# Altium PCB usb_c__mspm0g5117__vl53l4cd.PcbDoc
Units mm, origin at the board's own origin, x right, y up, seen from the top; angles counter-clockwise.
Board outline 68 x 40 mm, 2 copper layers (Top, Bottom), stack 0 mm thick; 34 components, 27 nets, 182 pads, 68 vias.
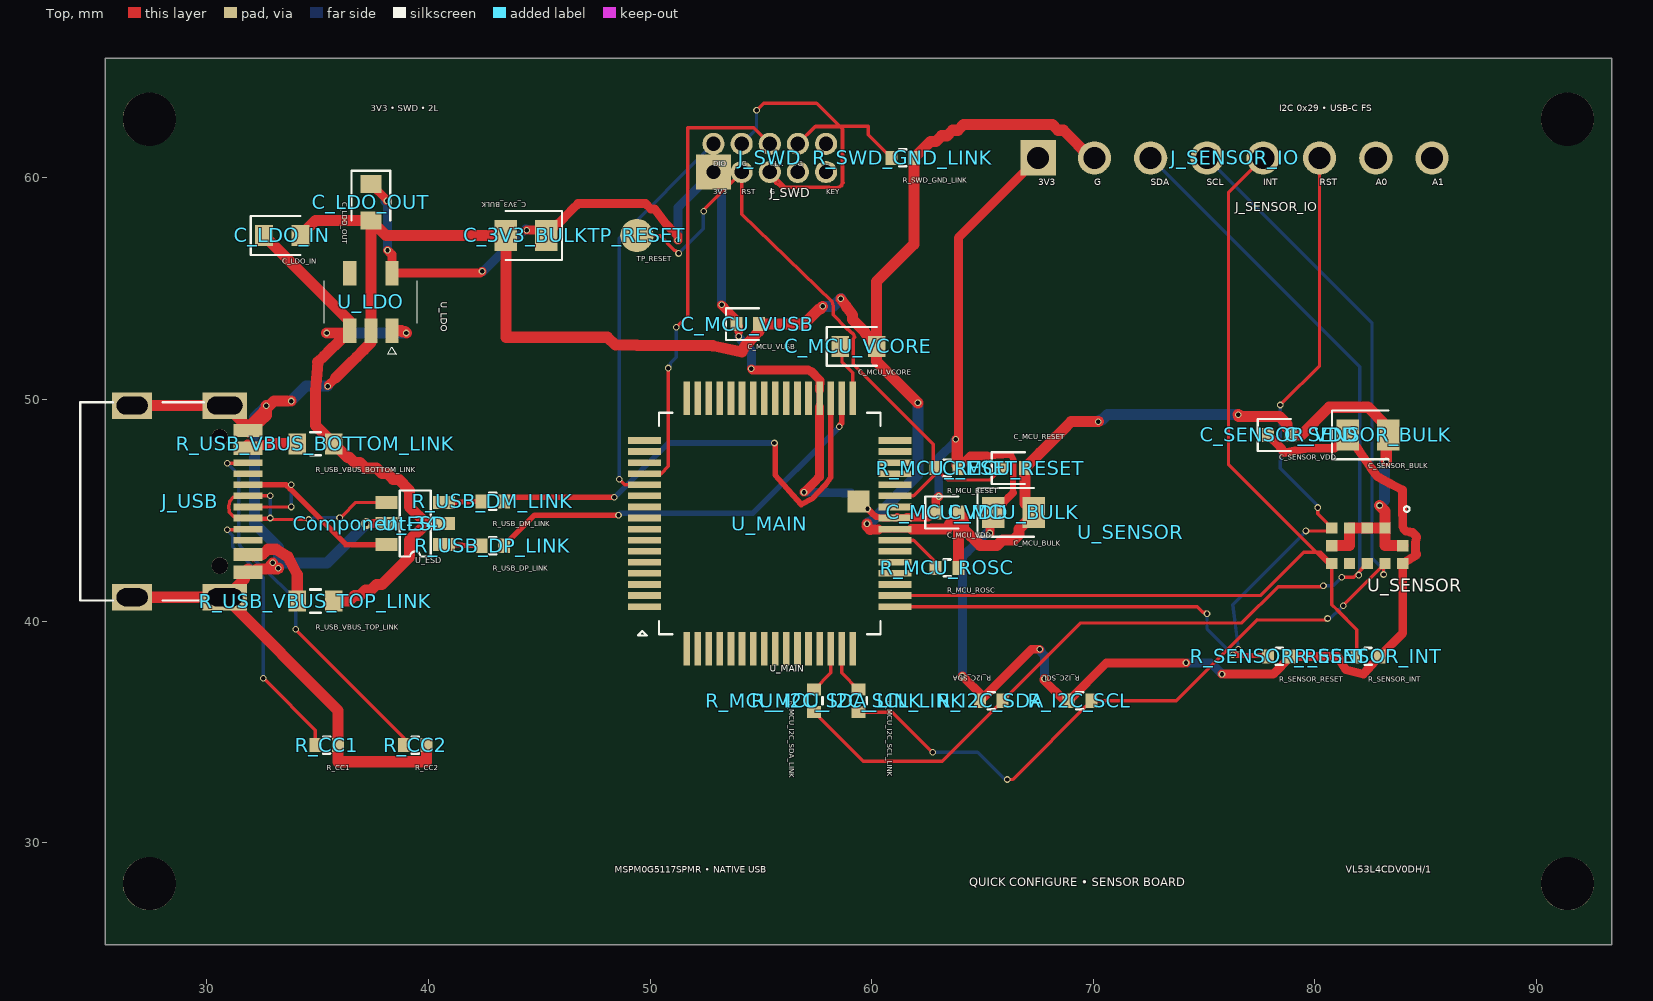
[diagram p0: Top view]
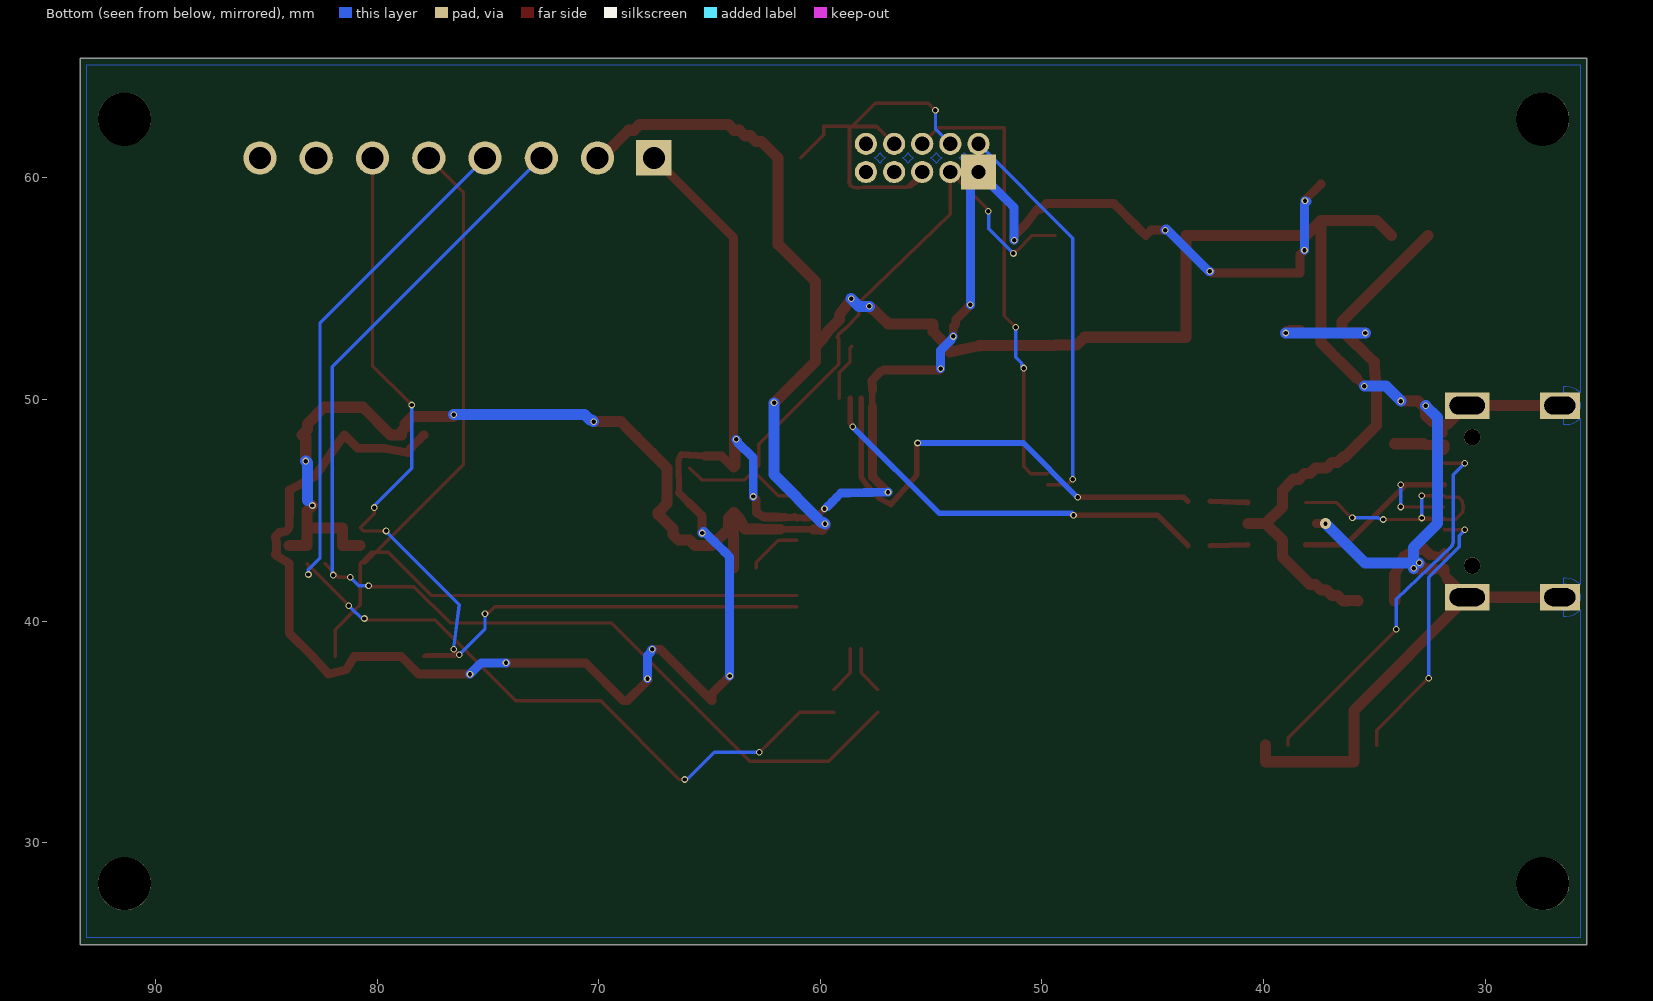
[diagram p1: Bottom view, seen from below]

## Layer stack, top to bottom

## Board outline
25.4,65.4 93.4,65.4 93.4,25.4 25.4,25.4

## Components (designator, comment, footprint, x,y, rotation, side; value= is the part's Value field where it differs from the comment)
C_3V3_BULK "" TSCIRCUIT-2.8500x1.4000mm 44.4,57.4 r180 top
C_LDO_IN "" TSCIRCUIT-2.4500x0.9500mm 33.4,57.4 r0 top
C_LDO_OUT "" TSCIRCUIT-0.9500x2.4500mm 37.4,58.9 r270 top
C_MCU_BULK "" TSCIRCUIT-2.8500x1.4000mm 66.4,44.9 r0 top
C_MCU_RESET "" TSCIRCUIT-1.5600x0.6400mm 66.4,46.9 r0 top
C_MCU_VCORE "" TSCIRCUIT-2.4500x0.9500mm 59.4,52.4 r0 top
C_MCU_VDD "" TSCIRCUIT-1.5600x0.6400mm 63.4,44.9 r0 top
C_MCU_VUSB "" TSCIRCUIT-1.5600x0.6400mm 54.4,53.4 r0 top
C_SENSOR_BULK "" TSCIRCUIT-2.8500x1.4000mm 82.4,48.4 r0 top
C_SENSOR_VDD "" TSCIRCUIT-1.5600x0.6400mm 78.4,48.4 r0 top
Component-34 "" TSCIRCUIT-0.5000x0.5000mm 37.2,44.4 r0 top
J_SENSOR_IO "" TSCIRCUIT-19.2800x1.5000mm 76.4,60.9 r0 top
J_SWD "" TSCIRCUIT-6.0800x2.2700mm 55.4,60.9 r0 top
J_USB "" TSCIRCUIT-6.7732x9.8502mm 29.112,45.4 r90 top
R_CC1 "" TSCIRCUIT-1.5600x0.6400mm 35.4,34.4 r0 top
R_CC2 "" TSCIRCUIT-1.5600x0.6400mm 39.4,34.4 r0 top
R_I2C_SCL "" TSCIRCUIT-1.5600x0.6400mm 69.4,36.4 r180 top
R_I2C_SDA "" TSCIRCUIT-1.5600x0.6400mm 65.4,36.4 r180 top
R_MCU_I2C_SCL_LINK "" TSCIRCUIT-0.6400x1.5600mm 59.4,36.4 r270 top
R_MCU_I2C_SDA_LINK "" TSCIRCUIT-0.6400x1.5600mm 57.4,36.4 r270 top
R_MCU_RESET "" TSCIRCUIT-1.5600x0.6400mm 63.4,46.9 r0 top
R_MCU_ROSC "" TSCIRCUIT-1.5600x0.6400mm 63.4,42.4 r0 top
R_SENSOR_INT "" TSCIRCUIT-1.5600x0.6400mm 82.4,38.4 r0 top
R_SENSOR_RESET "" TSCIRCUIT-1.5600x0.6400mm 78.4,38.4 r0 top
R_SWD_GND_LINK "" TSCIRCUIT-1.5600x0.6400mm 61.4,60.9 r0 top
R_USB_DM_LINK "" TSCIRCUIT-1.5600x0.6400mm 42.9,45.4 r0 top
R_USB_DP_LINK "" TSCIRCUIT-1.5600x0.6400mm 42.9,43.4 r0 top
R_USB_VBUS_BOTTOM_LINK "" TSCIRCUIT-2.4500x0.9500mm 34.9,48 r0 top
R_USB_VBUS_TOP_LINK "" TSCIRCUIT-2.4500x0.9500mm 34.9,40.9 r0 top
TP_RESET "" TSCIRCUIT-1.5000x1.5000mm 49.4,57.4 r0 top
U_ESD "" TSCIRCUIT-3.6000x2.5000mm 39.4,44.4 r0 top
U_LDO "" TSCIRCUIT-2.5000x3.7000mm 37.4,54.4 r270 top
U_MAIN "" TSCIRCUIT-12.8000x12.8000mm 55.4,44.4 r0 top
U_SENSOR "" TSCIRCUIT-3.7081x2.1079mm 82.368,43.4 r0 top

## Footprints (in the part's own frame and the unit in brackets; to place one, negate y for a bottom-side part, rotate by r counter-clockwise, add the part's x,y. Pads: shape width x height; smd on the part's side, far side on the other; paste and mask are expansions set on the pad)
TSCIRCUIT-0.5000x0.5000mm [mm]
TSCIRCUIT-0.6400x1.5600mm [mm]
  rect 0.54x0.64 smd: 1(-0.51,0) 2(0.51,0)
  silkscreen extent -0.15,-0.38 0.15,0.38
TSCIRCUIT-0.9500x2.4500mm [mm]
  rect 0.8x0.95 smd: 1(-0.825,0) 2(0.825,0)
  silkscreen extent -1.43,-0.87 0.82,0.88
TSCIRCUIT-1.5000x1.5000mm [mm]
  round 1.5 smd: 1(0,0)
TSCIRCUIT-1.5600x0.6400mm [mm]
  rect 0.54x0.64 smd: 1(-0.51,0) 2(0.51,0)
  silkscreen extent -0.98,-0.72 0.51,0.72
TSCIRCUIT-2.4500x0.9500mm [mm]
  rect 0.8x0.95 smd: 1(-0.825,0) 2(0.825,0)
  silkscreen extent -1.42,-0.87 0.82,0.87
TSCIRCUIT-2.5000x3.7000mm [mm]
  rect 1.1x0.6 smd: 1(1.3,0.95) 2(1.3,0) 3(1.3,-0.95) 4(-1.3,-0.95) 5(-1.3,0.95)
  silkscreen extent -0.95,-2.1 2.35,2.1
TSCIRCUIT-2.8500x1.4000mm [mm]
  rect 1.025x1.4 smd: 1(-0.913,0) 2(0.913,0)
  silkscreen extent -1.63,-1.1 0.91,1.1
TSCIRCUIT-3.6000x2.5000mm [mm]
  rect 1x0.6 smd: 1(-1.3,-0.95) 2(-1.3,0) 3(-1.3,0.95) 4(1.3,0.95) 5(1.3,0) 6(1.3,-0.95)
  silkscreen extent -0.7,-1.49 0.7,1.49
TSCIRCUIT-3.7081x2.1079mm [mil]
  rect 39.37x39.37 smd: 1(-904.26,78.75)
  rect 20x20 smd: 2(31.49,31.49) 3(-0.01,31.49) 4(-31.49,31.49) 5(-62.99,31.49) 6(-62.99,0) 7(-62.99,-31.5) 8(-31.49,-31.5) 9(-0.01,-31.5) 10(31.49,-31.5) 11(62.99,-31.5) 12(62.99,0)
  silkscreen extent 65,60 75,70
TSCIRCUIT-6.0800x2.2700mm [mm]
  rect 1.6x1.6 hole 0.65: 1(-2.54,-0.635)
  round 1 hole 0.65: 2(-2.54,0.635) 3(-1.27,0.635) 4(0,0.635) 5(1.27,0.635) 6(2.54,0.635) 7(2.54,-0.635) 8(1.27,-0.635) 9(0,-0.635) 10(-1.27,-0.635)
TSCIRCUIT-6.7732x9.8502mm [mm]
  rect 0.3x1.3 smd: 1(-3.35,-2.737) 2(-3.05,-2.737) 3(-2.55,-2.737) 4(-2.25,-2.737) 5(-1.75,-2.737) 6(-1.25,-2.737) 7(-0.75,-2.737) 8(-0.25,-2.737) 9(0.25,-2.737) 10(0.75,-2.737) 11(1.25,-2.737) 12(1.75,-2.737) 13(2.55,-2.737) 14(2.25,-2.737) 15(3.35,-2.737) 16(3.05,-2.737)
  rect 1.2x2 hole 0.8 slot 1.6 at 90 deg: 17(-4.325,-1.693) 18(4.325,-1.693)
  rect 1.2x1.8 hole 0.8 slot 1.4 at 90 deg: 19(4.325,2.487) 20(-4.325,2.487)
  round 0.75 hole 0.75 unplated: NPTH-1(-2.9,-1.468) NPTH-2(2.9,-1.468)
  silkscreen extent -4.47,-0.75 4.47,4.83
TSCIRCUIT-12.8000x12.8000mm [mm]
  rect 1.5x0.3 smd: 1(-5.65,-3.75) 2(-5.65,-3.25) 3(-5.65,-2.75) 4(-5.65,-2.25) 5(-5.65,-1.75) 6(-5.65,-1.25) 7(-5.65,-0.75) 8(-5.65,-0.25) 9(-5.65,0.25) 10(-5.65,0.75) 11(-5.65,1.25) 12(-5.65,1.75) 13(-5.65,2.25) 14(-5.65,2.75) 15(-5.65,3.25) 16(-5.65,3.75) 33(5.65,3.75) 34(5.65,3.25) 35(5.65,2.75) 36(5.65,2.25) 37(5.65,1.75) 38(5.65,1.25) 39(5.65,0.75) 40(5.65,0.25) 41(5.65,-0.25) 42(5.65,-0.75) 43(5.65,-1.25) 44(5.65,-1.75) 45(5.65,-2.25) 46(5.65,-2.75) 47(5.65,-3.25) 48(5.65,-3.75)
  rect 0.3x1.5 smd: 17(-3.75,5.65) 18(-3.25,5.65) 19(-2.75,5.65) 20(-2.25,5.65) 21(-1.75,5.65) 22(-1.25,5.65) 23(-0.75,5.65) 24(-0.25,5.65) 25(0.25,5.65) 26(0.75,5.65) 27(1.25,5.65) 28(1.75,5.65) 29(2.25,5.65) 30(2.75,5.65) 31(3.25,5.65) 32(3.75,5.65) 49(3.75,-5.65) 50(3.25,-5.65) 51(2.75,-5.65) 52(2.25,-5.65) 53(1.75,-5.65) 54(1.25,-5.65) 55(0.75,-5.65) 56(0.25,-5.65) 57(-0.25,-5.65) 58(-0.75,-5.65) 59(-1.25,-5.65) 60(-1.75,-5.65) 61(-2.25,-5.65) 62(-2.75,-5.65) 63(-3.25,-5.65) 64(-3.75,-5.65)
  silkscreen extent -5.95,-5.05 5,5
TSCIRCUIT-19.2800x1.5000mm [mm]
  rect 1.6x1.6 hole 1: 1(-8.89,0)
  round 1.5 hole 1: 2(-6.35,0) 3(-3.81,0) 4(-1.27,0) 5(1.27,0) 6(3.81,0) 7(6.35,0) 8(8.89,0)

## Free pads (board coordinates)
  round 2.4 hole 2.4 unplated: NPTH-3(27.4,28.15) NPTH-4(91.4,28.15) NPTH-5(27.4,62.65) NPTH-6(91.4,62.65)

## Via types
v1: diameter 0.3, hole 0.2, Top to Bottom, 67 vias
v2: diameter 0.5, hole 0.2, Top to Bottom, 1 vias

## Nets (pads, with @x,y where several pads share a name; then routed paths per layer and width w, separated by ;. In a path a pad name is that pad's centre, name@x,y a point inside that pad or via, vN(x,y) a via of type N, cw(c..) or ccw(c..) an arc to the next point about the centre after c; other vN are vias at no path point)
".J_SWD > .pin2 to .U_MAIN > .pin12": J_SWD.2 U_MAIN.12 | length 18.2
  Top w0.15: v1(48.6,46.4) 48.603,46.397 48.85,46.15 U_MAIN.12
  Bottom w0.15: v1(48.6,46.4) 48.6,57.275 J_SWD.2
".J_SWD > .pin4 to .U_MAIN > .pin13": J_SWD.4 U_MAIN.13 | length 20.9
  Top w0.15: U_MAIN.13 49.754,46.654 50.495,46.654 50.823,46.982 v1(50.823,51.418) ; v1(51.185,53.26) 51.243,53.318 51.692,53.767 51.692,62.257 54.678,62.257 J_SWD.4
  Bottom w0.15: v1(50.823,51.418) 50.914,51.509 50.914,51.624 51.185,51.895 v1(51.185,53.26)
".U_MAIN > .pin42 to .R_MCU_ROSC > .pin1": R_MCU_ROSC.1 U_MAIN.42 | length 2.5
  Top w0.15: U_MAIN.42 61.889,43.65 62.89,42.649 R_MCU_ROSC.1
GND: C_3V3_BULK.2 C_LDO_IN.2 C_LDO_OUT.2 C_MCU_BULK.2 C_MCU_RESET.2 C_MCU_VCORE.2 C_MCU_VDD.2 C_MCU_VUSB.2 C_SENSOR_BULK.2 C_SENSOR_VDD.2 J_SENSOR_IO.2 J_USB.1 J_USB.2 J_USB.15 J_USB.16 J_USB.17 J_USB.18 J_USB.19 J_USB.20 R_CC1.2 R_CC2.2 R_MCU_ROSC.2 R_SWD_GND_LINK.2 U_ESD.2 U_LDO.2 U_MAIN.41 U_SENSOR.2 U_SENSOR.3 U_SENSOR.4 U_SENSOR.6 U_SENSOR.12 | length 161.6
  Top w0.275: J_USB.2 J_USB.2@32.266,42.35 ; J_USB.16 32.125,48.726 32.401,49.002
  Top w0.3: J_USB.1@31.699,41.9 J_USB.1 J_USB.1@31.849,42.2 ; J_USB.15@31.699,48.9 J_USB.15 ; J_USB.16@31.849,48.6 J_USB.15 ; J_USB.2@31.884,42.324 32.33,42.343 J_USB.2@32.499,42.343 ; J_USB.15@31.999,48.9 J_USB.15 ; U_MAIN.41@60.3,44.135 61.035,44.135 U_MAIN.41 61.144,44.15 61.238,44.15 61.331,44.15 61.425,44.15 61.519,44.15 61.613,44.15 61.706,44.15 61.8,44.15
  Top w0.325: J_USB.2 J_USB.2@31.884,42.324 ; J_USB.16 J_USB.16@31.849,48.6
  Top w0.35: v1(35.447,50.6) 35.481,50.634 v1@35.481,50.645
  Top w0.4: v1@35.481,50.645 35.801,50.965 ; 37.2,44.4 U_ESD.2@37.6,44.4
  Top w0.45: 59.935,44.135 60.3,44.135
  Top w0.475: 32.499,42.343 32.693,42.343 v1(32.975,42.625) ; v1(58.608,54.548) 58.867,54.184 ; 61.8,44.15 62.253,44.15 62.707,44.15
  Top w0.5: J_USB.20 J_USB.17 ; J_USB.19 J_USB.18 ; J_USB.18 30.874,49.725 31.474,49.125 31.699,48.9 ; 31.699,41.9 31.474,41.675 30.874,41.075 J_USB.17 35.91,35.971 R_CC1.2 35.91,33.65 39.91,33.65 R_CC2.2 ; J_USB.1@31.849,42.2 J_USB.2 ; 31.999,48.9 33.028,49.929 v1(33.802,49.929) ; J_USB.2@32.266,42.35 32.682,42.35 33.099,42.35 33.189,42.35 v1(33.22,42.382) ; 32.401,49.002 32.677,49.278 v1(32.677,49.716) ; C_LDO_IN.2 34.9,58.075 C_LDO_OUT.2 ; 35.801,50.965 36.121,51.285 36.44,51.604 36.76,51.924 37.08,52.244 37.4,52.564 37.4,52.832 U_LDO.2 C_LDO_OUT.2 ; v1(57.789,54.2) 57.68,54.091 57.624,54.091 57.278,53.746 56.933,53.4 56.528,53.4 56.124,53.4 55.719,53.4 55.315,53.4 C_MCU_VUSB.2 54.91,53.075 54.6,52.745 54.289,52.414 54.15,52.15 52.825,52.423 52.337,52.427 51.849,52.43 51.361,52.433 50.873,52.436 50.385,52.44 49.897,52.443 49.409,52.446 48.921,52.449 48.433,52.453 48.079,52.806 43.488,52.806 C_3V3_BULK.2 38.075,57.4 C_LDO_OUT.2 ; 58.867,54.184 59.127,53.819 59.127,53.61 59.645,53.091 59.905,52.727 59.905,52.72 C_MCU_VCORE.2 ; v1(59.789,44.388) 59.789,44.281 59.935,44.135 ; v1(62.087,49.846) 60.225,51.708 C_MCU_VCORE.2 ; 62.707,44.15 63.4,44.15 63.66,44.65 C_MCU_VDD.2 ; R_MCU_ROSC.2 C_MCU_VDD.2 ; J_SENSOR_IO.2 69.9,60.9 68.65,62.15 68.4,62.15 68.15,62.4 64.15,62.4 63.9,62.15 63.65,62.15 63.4,61.9 63.15,61.9 62.9,61.65 62.65,61.65 62.65,61.64 62.579,61.569 62.244,61.234 R_SWD_GND_LINK.2 61.91,57.006 60.225,55.321 60.225,54.834 60.225,54.347 60.225,53.86 60.225,53.374 60.225,52.887 C_MCU_VCORE.2 ; v1(70.232,48.996) 69.823,48.996 69.415,48.996 69.006,48.996 68.657,48.647 68.307,48.297 67.958,47.948 67.609,47.599 67.259,47.249 C_MCU_RESET.2 66.91,45.303 C_MCU_BULK.2 67.312,44.813 66.65,44.15 66.65,43.9 66.4,43.65 65.9,43.65 65.65,43.4 64.9,43.4 64.15,44.15 64.15,44.65 63.9,44.9 C_MCU_VDD.2 ; v1(76.544,49.316) 76.567,49.293 76.567,49.233 78.4,49.233 78.733,48.9 78.733,48.733 78.91,48.557 C_SENSOR_VDD.2 79.4,48.4 80.65,49.65 82.4,49.65 83.15,48.9 83.15,48.65 83.4,48.4 C_SENSOR_BULK.2 83.221,48.309 v1(83.221,47.221) ; U_SENSOR.6 81.568,43.4 U_SENSOR.4 U_SENSOR.3 U_SENSOR.2 ; v1(82.921,45.214) 83.168,44.967 U_SENSOR.2 83.168,43.4 U_SENSOR.12
  Bottom w0.325: v1(82.921,45.214) 83.142,45.435
  Bottom w0.5: v1(32.677,49.716) 32.15,49.189 32.15,44.4 33.22,43.326 33.22,42.854 v1(33.22,42.382) ; v1(32.975,42.625) 35.425,42.625 37.2,44.4 ; v1(33.802,49.929) 34.473,50.6 v1(35.447,50.6) ; v1(57.789,54.2) 58.259,54.2 v1(58.608,54.548) ; v1(59.789,44.388) 59.855,44.455 59.935,44.455 62.087,46.606 v1(62.087,49.846) ; v1(70.232,48.996) 70.312,49.076 70.394,49.076 70.635,49.316 71.127,49.316 71.62,49.316 72.112,49.316 72.604,49.316 73.097,49.316 73.589,49.316 74.082,49.316 74.574,49.316 75.067,49.316 75.559,49.316 76.052,49.316 v1(76.544,49.316) ; 83.142,45.435 83.142,47.142 v1(83.221,47.221)
MAIN_RESET: C_MCU_RESET.1 J_SWD.10 R_MCU_RESET.1 TP_RESET.1 U_MAIN.38 | length 30.1
  Top w0.15: TP_RESET.1 50.438,57.4 51.118,56.72 51.153,56.72 v1(51.283,56.59) ; v1(52.416,58.495) 52.416,58.551 J_SWD.10 54.13,58.355 58.219,54.4 58.258,54.229 58.258,53.823 58.858,53.224 59.185,52.933 59.235,52.803 59.17,52.737 59.17,51.599 62.783,47.986 62.783,47.007 R_MCU_RESET.1 ; U_MAIN.38 61.889,45.65 62.89,46.651 R_MCU_RESET.1 ; C_MCU_RESET.1 65.359,46.369 63.421,46.369 R_MCU_RESET.1
  Bottom w0.15: v1(51.283,56.59) 52.391,57.698 52.391,58.38 52.391,58.47 v1(52.416,58.495)
MCU_I2C_SCL_LOCAL: R_MCU_I2C_SCL_LINK.1 U_MAIN.50 | length 2.2
  Top w0.15: U_MAIN.50 58.65,37.66 R_MCU_I2C_SCL_LINK.1
MCU_I2C_SDA_LOCAL: R_MCU_I2C_SDA_LINK.1 U_MAIN.51 | length 2.2
  Top w0.15: R_MCU_I2C_SDA_LINK.1 58.15,37.66 U_MAIN.51
MSPM0_VCORE: C_MCU_VCORE.1 U_MAIN.32 | length 2.6
  Top w0.15: C_MCU_VCORE.1 58.663,52.312 58.663,51.687 59.15,51.199 U_MAIN.32
SENSOR_ADDR0: J_SENSOR_IO.7
SENSOR_ADDR1: J_SENSOR_IO.8
SENSOR_INT: J_SENSOR_IO.5 R_SENSOR_INT.1 U_MAIN.47 U_SENSOR.7 | length 46.4
  Top w0.15: U_MAIN.47 77.529,41.15 79.488,43.109 80.259,43.109 U_SENSOR.7 ; J_SENSOR_IO.5 76.101,59.331 76.101,47.066 80.542,42.625 80.743,42.625 U_SENSOR.7 ; R_SENSOR_INT.1 81.89,39.615 80.979,40.521 80.768,40.738 U_SENSOR.7
SENSOR_RESET: J_SENSOR_IO.6 R_SENSOR_RESET.1 U_MAIN.48 U_SENSOR.5 | length 46.5
  Top w0.15: U_MAIN.48 74.692,40.65 74.945,40.397 75.069,40.397 v1(75.134,40.332) ; v1(76.295,38.479) 77.811,38.479 R_SENSOR_RESET.1 76.465,38.4 76.412,38.453 76.321,38.453 v1(76.55,38.725) ; v1(78.435,49.75) 78.529,49.844 78.529,49.847 80.21,51.528 J_SENSOR_IO.6 ; v1(79.598,44.066) 80.634,44.066 U_SENSOR.5 80.127,44.841 v1(80.127,45.122)
  Bottom w0.15: v1(75.134,40.332) 75.134,39.64 76.233,38.541 v1(76.295,38.479) ; v1(76.55,38.725) 76.295,40.744 79.466,43.915 79.466,43.933 v1(79.598,44.066) ; v1(78.435,49.75) 78.435,46.891 80.173,45.153 80.158,45.153 v1(80.127,45.122)
SENSOR_SCL: J_SENSOR_IO.4 R_I2C_SCL.1 R_MCU_I2C_SCL_LINK.2 U_SENSOR.10 | length 51.7
  Top w0.15: R_MCU_I2C_SCL_LINK.2 60.923,35.89 62.674,34.138 62.702,34.138 v1(62.756,34.084) ; v1(66.116,32.848) 66.358,32.848 R_I2C_SCL.1 73.743,36.404 77.391,40.058 80.397,40.051 80.51,40.051 v1(80.574,40.115) ; v1(81.283,40.698) 81.28,40.712 U_SENSOR.10 83.1,42.532 v1(83.1,42.1)
  Bottom w0.15: v1(62.756,34.084) 64.778,34.084 65.999,32.863 66.101,32.863 v1(66.116,32.848) ; J_SENSOR_IO.4 82.581,53.448 82.58,42.849 82.582,42.841 83.106,42.316 83.106,42.106 v1(83.1,42.1) ; v1(80.574,40.115) 80.697,40.115 81.139,40.557 81.142,40.557 v1(81.283,40.698)
SENSOR_SDA: J_SENSOR_IO.3 R_I2C_SDA.1 R_MCU_I2C_SDA_LINK.2 U_SENSOR.9 | length 53
  Top w0.15: R_MCU_I2C_SDA_LINK.2 59.615,33.675 63.185,33.675 R_I2C_SDA.1 69.424,39.914 76.704,39.914 78.345,41.554 80.273,41.554 80.355,41.554 v1(80.388,41.587) ; v1(81.221,41.983) 81.751,41.983 U_SENSOR.9 81.977,42.209 v1(81.977,42.076)
  Bottom w0.15: J_SENSOR_IO.3 82.021,51.469 82.021,42.12 v1(81.977,42.076) ; v1(80.388,41.587) 80.825,41.587 v1@81.22,41.982
swd-ground-1-to-2: J_SWD.3 J_SWD.5 J_SWD.9 R_SWD_GND_LINK.1 | length 26.3
  Top w0.15: v1(54.804,63.048) 54.876,63.12 54.884,63.12 55.135,63.37 57.51,63.37 58.709,62.172 58.709,59.869 58.712,59.771 58.527,59.58 58.296,59.566 58.098,59.575 ; R_SWD_GND_LINK.1 59.841,61.949 59.841,62.329 57.464,62.329 J_SWD.5 57.436,62.301 58.603,62.301 58.659,62.245 58.659,59.857 58.652,59.632 58.318,59.529 58.098,59.575 ; 56.7,59.575 57.101,59.569 57.3,59.579 57.7,59.567 58.098,59.575 ; 56.7,59.575 56.3,59.57 56.098,59.578 56.065,59.6 J_SWD.9 55.675,59.765 55.9,59.6 56.098,59.579 56.299,59.567 56.5,59.575 56.7,59.575 ; 56.7,59.575 57.1,59.575 57.5,59.572 57.7,59.575 58.098,59.575
  Bottom w0.15: J_SWD.3 54.804,62.209 v1(54.804,63.048)
usb-dm-device: R_USB_DM_LINK.1 U_ESD.4 | length 1.7
  Top w0.25: U_ESD.4 R_USB_DM_LINK.1
usb-dm-mcu: R_USB_DM_LINK.2 U_MAIN.30 | length 21.9
  Top w0.25: R_USB_DM_LINK.2 43.589,45.579 v1(48.383,45.579) ; v1(55.612,48.035) 55.645,48.002 55.645,47.874 55.639,46.596 56.816,45.254 57.336,45.537 57.9,46.136 58.156,46.489 U_MAIN.30
  Bottom w0.25: v1(48.383,45.579) 50.839,48.035 v1(55.612,48.035)
usb-dm-port-tie: J_USB.7 J_USB.9 U_ESD.3 | length 12
  Top w0.15: J_USB.7 v1(32.85,44.65) ; v1(32.85,45.65) J_USB.9 31.783,45.584 31.19,45.584 31.188,45.578 31.025,45.415 30.991,45.198 31.01,44.908 31.328,44.591 v1(34.59,44.581) ; v1(35.984,44.665) 36.058,44.739 36.103,44.739 36.715,45.35 U_ESD.3
  Bottom w0.15: v1(32.85,44.65) v1(32.85,45.65) ; v1(34.59,44.581) 34.618,44.609 34.758,44.609 34.814,44.665 v1(35.984,44.665)
usb-dp-device: R_USB_DP_LINK.1 U_ESD.6 | length 1.7
  Top w0.25: U_ESD.6 R_USB_DP_LINK.1
usb-dp-mcu: R_USB_DP_LINK.2 U_MAIN.31 | length 18.7
  Top w0.25: R_USB_DP_LINK.2 44.791,44.781 v1(48.574,44.781) ; v1(58.542,48.769) 58.559,48.797 58.559,48.838 58.65,48.928 U_MAIN.31
  Bottom w0.25: v1(48.574,44.781) 48.653,44.86 54.622,44.86 v1(58.542,48.769)
usb-dp-port-tie: J_USB.8 J_USB.10 U_ESD.1 | length 12.3
  Top w0.15: J_USB.8 v1(33.8,45.15) ; J_USB.10 v1(33.8,46.15)
  Top w0.25: J_USB.10 33.564,46.15 33.77,45.954 36.268,43.454 U_ESD.1
  Bottom w0.15: v1(33.8,45.15) v1(33.8,46.15)
USB_CC1: J_USB.6 R_CC1.1 | length 12.3
  Top w0.15: v1(30.918,44.126) 31.825,44.126 J_USB.6 ; v1(32.541,37.42) 32.711,37.25 32.718,37.25 34.89,35.078 R_CC1.1
  Bottom w0.15: v1(30.918,44.126) 31.014,44.03 31.014,44.004 31.16,43.857 31.16,43.346 32.541,41.965 v1(32.541,37.42)
USB_CC2: J_USB.12 R_CC2.1 | length 17
  Top w0.15: v1(30.918,47.126) 31.825,47.126 J_USB.12 ; v1(34.008,39.625) 34.015,39.618 38.89,34.743 R_CC2.1
  Bottom w0.15: v1(30.918,47.126) 30.944,47.1 31.432,46.612 31.432,43.556 31.5,43.375 34.008,40.98 v1(34.008,39.625)
USB_VBUS_BOTTOM_LOCAL: J_USB.13 J_USB.14 R_USB_VBUS_BOTTOM_LINK.1 | length 2.5
  Top w0.3: J_USB.14 J_USB.14@31.849,47.8 ; J_USB.13 J_USB.13@32.499,47.95
  Top w0.437: 32.72,47.95 32.769,48
  Top w0.45: 32.499,47.95 32.72,47.95
  Top w0.475: J_USB.13@31.849,47.8 J_USB.13
  Top w0.5: 32.769,48 33.205,48 33.64,48 R_USB_VBUS_BOTTOM_LINK.1
USB_VBUS_TOP_LOCAL: J_USB.3 J_USB.4 R_USB_VBUS_TOP_LINK.1 | length 4.4
  Top w0.3: J_USB.4 31.849,43 J_USB.3 31.9,42.9 J_USB.3@32.1,42.9
  Top w0.425: J_USB.3@32.1,42.9 32.5,43
  Top w0.5: 32.5,43 32.76,43.24 33.12,43.24 33.65,42.9 34.075,42.101 34.075,41.7 34.075,41.3 R_USB_VBUS_TOP_LINK.1
VBUS5: C_LDO_IN.1 R_USB_VBUS_BOTTOM_LINK.2 R_USB_VBUS_TOP_LINK.2 U_ESD.5 U_LDO.1 U_LDO.3 | length 31.2
  Top w0.5: C_LDO_IN.1 36.45,53.525 U_LDO.3 ; v1(35.4,53) 36.35,53 U_LDO.3 ; R_USB_VBUS_TOP_LINK.2 35.751,40.926 36.232,40.926 36.207,40.9 36.4,40.9 36.65,41.15 36.9,41.15 37.15,41.4 37.4,41.4 37.65,41.65 37.9,41.65 39.15,42.9 39.15,43.65 39.9,44.4 ; U_LDO.1 38.787,53.1 38.832,53.056 38.944,53.056 v1(39,53) ; U_LDO.3 36.16,52.817 35.871,52.535 35.581,52.252 35.291,51.969 35.002,51.686 34.9,50.4 34.9,48.825 R_USB_VBUS_BOTTOM_LINK.2 36.036,47.692 36.346,47.384 36.363,47.4 36.4,47.4 36.65,47.15 36.9,47.15 37.15,46.9 37.65,46.9 37.9,46.65 38.15,46.65 38.4,46.4 38.65,46.4 39.15,45.9 39.15,45.15 39.9,44.4 ; 39.9,44.4 U_ESD.5 39.9,44.4
  Bottom w0.5: v1(35.4,53) v1(39,53)
VCC_3V3: C_3V3_BULK.1 C_LDO_OUT.1 C_MCU_BULK.1 C_MCU_VDD.1 C_MCU_VUSB.1 C_SENSOR_BULK.1 C_SENSOR_VDD.1 J_SENSOR_IO.1 J_SWD.1 R_I2C_SCL.2 R_I2C_SDA.2 R_MCU_RESET.2 R_SENSOR_INT.2 R_SENSOR_RESET.2 U_LDO.5 U_MAIN.29 U_MAIN.40 U_SENSOR.1 U_SENSOR.11 | length 123.1
  Top w0.092: 83.968,44.254 83.968,44.2 84.014,44.154
  Top w0.176: 84.114,44.054 84.136,44.032 84.286,44.014
  Top w0.262: 66.382,45.794 66.382,46.153 66.382,46.513 66.4,46.525
  Top w0.275: 66.275,47.525 66.4,47.275 66.4,46.9 66.4,46.525
  Top w0.3: v1(54,52.843) 54,53.067 ; U_MAIN.29 U_MAIN.29@57.65,50.424 ; v1(59.812,45.065) 60.006,44.882 60.2,44.7 U_MAIN.40@60.506,44.657 ; U_MAIN.40@60.778,44.654 U_MAIN.40
  Top w0.303: U_MAIN.29@57.649,49.656 U_MAIN.29
  Top w0.312: 65.198,47.455 65.561,47.474 65.923,47.493 66.275,47.525
  Top w0.321: U_MAIN.40@60.506,44.657 U_MAIN.40@60.778,44.654
  Top w0.327: U_MAIN.40@61.162,44.705 61.26,44.677 U_MAIN.40@61.583,44.683
  Top w0.337: U_MAIN.40 U_MAIN.40@61.162,44.705
  Top w0.35: C_MCU_BULK.1@65.935,45.347 66.158,45.57 66.382,45.794
  Top w0.387: U_MAIN.40@61.583,44.683 61.905,44.689
  Top w0.4: C_LDO_OUT.1 38.125,59 v1(38.125,58.965) ; v1(38.149,56.736) 38.233,56.651 38.35,56.535 U_LDO.5 42.32,55.7 42.338,55.718 42.351,55.718 v1(42.415,55.782) ; v1(44.438,57.641) 45.072,57.641 C_3V3_BULK.1 45.552,57.64 45.792,57.879 46.032,58.119 46.271,58.359 46.511,58.598 46.751,58.838 47.132,58.838 47.512,58.838 47.893,58.838 48.273,58.838 48.654,58.838 49.035,58.838 49.415,58.838 49.796,58.838 50.039,58.595 50.2,58.6 50.768,57.866 51.011,57.623 51.254,57.38 v1(51.254,57.193) ; v1(53.229,54.267) 53.329,54.167 53.89,53.606 C_MCU_VUSB.1 54,53.29 54,53.067 ; v1(54.572,51.384) 54.622,51.334 54.627,51.329 54.983,51.329 55.339,51.329 55.695,51.329 56.051,51.329 56.407,51.329 56.763,51.329 57.119,51.329 57.267,51.267 57.667,50.867 U_MAIN.29@57.65,50.424 ; v1(56.945,45.818) 56.984,45.837 56.985,45.839 57.204,46.061 57.423,46.284 57.643,46.506 57.644,46.899 57.644,47.293 57.645,47.687 57.646,48.081 57.647,48.475 57.648,48.869 57.648,49.262 U_MAIN.29@57.649,49.656 ; 61.905,44.689 62.228,44.694 62.55,44.7 C_MCU_VDD.1 62.89,45.484 63.007,45.601 v1(63.028,45.622) ; v1(63.8,48.2) 63.8,47.01 R_MCU_RESET.2 ; v1(64.09,37.52) 64.233,37.377 64.452,37.158 64.671,36.939 64.89,36.72 R_I2C_SDA.2 67.218,38.728 v1(67.584,38.728) ; 65.198,47.455 64.825,47.448 64.451,47.441 64.181,47.171 R_MCU_RESET.2 ; v1(65.335,43.974) 65.335,44.361 65.335,44.747 C_MCU_BULK.1 65.711,45.123 C_MCU_BULK.1@65.935,45.347 ; J_SENSOR_IO.1 63.91,57.3 R_MCU_RESET.2 ; v1(67.8,37.4) 67.775,37.375 67.775,37.329 68.704,36.4 R_I2C_SCL.2 70.599,38.109 74.182,38.109 v1(74.185,38.112) ; v1(75.81,37.604) 78.114,37.604 R_SENSOR_RESET.2 79.264,38.4 79.619,38.4 79.973,38.4 80.327,38.4 80.682,38.4 81.036,38.4 81.4,37.8 82.2,37.6 R_SENSOR_INT.2 83.968,39.458 U_SENSOR.11 84.6,43 84.536,43.168 84.536,43.516 84.6,43.8 84.4,44 84.286,44.014 ; C_SENSOR_VDD.1 78.09,48.2 78.29,48 78.49,47.8 78.6,47.6 79.689,47.8 80.088,47.8 80.488,47.8 80.888,47.8 81.088,48 81.288,48.2 C_SENSOR_BULK.1 81.709,48.087 81.93,47.773 82.151,47.46 82.373,47.147 82.594,46.833 82.815,46.52 83.1,46.367 83.385,46.213 83.671,46.06 83.956,45.907 83.958,45.566 83.961,45.224 83.963,44.883 83.966,44.541 83.968,44.254 ; 84.014,44.154 84.114,44.054
  Bottom w0.325: 59.677,45.165 59.708,45.165 v1(59.812,45.065)
  Bottom w0.4: v1(38.125,58.965) 38.093,58.933 38.024,58.933 38.149,58.808 v1(38.149,56.736) ; v1(42.415,55.782) 42.468,55.782 44.374,57.687 44.392,57.687 v1(44.438,57.641) ; v1(51.254,57.193) 51.261,57.2 51.261,57.566 51.261,57.933 51.261,58.299 51.261,58.666 51.527,58.932 51.794,59.199 52.06,59.465 52.327,59.732 52.593,59.998 J_SWD.1 53.229,59.896 v1(53.229,54.267) ; v1(54,52.843) 54.099,52.701 54.099,52.687 54.335,52.45 54.572,52.213 54.572,51.937 54.572,51.66 v1(54.572,51.384) ; v1(56.945,45.818) 57.298,45.811 57.651,45.805 58.005,45.798 58.358,45.791 58.711,45.785 59.064,45.778 59.269,45.574 59.473,45.37 59.677,45.165 ; v1(63.028,45.622) 63.028,47.365 63.74,48.076 63.74,48.14 v1(63.8,48.2) ; v1(64.09,37.52) 64.09,37.904 64.09,38.287 64.09,38.671 64.09,39.055 64.09,39.438 64.09,39.822 64.09,40.206 64.09,40.589 64.09,40.973 64.09,41.357 64.09,41.74 64.09,42.124 64.09,42.507 64.09,42.891 64.32,43.121 64.55,43.352 64.781,43.582 65.011,43.812 65.241,44.042 65.267,44.042 v1(65.335,43.974) ; v1(67.584,38.728) 67.651,38.661 67.651,38.587 67.8,38.439 v1(67.8,37.4) ; v1(74.185,38.112) 75.302,38.112 75.748,37.666 v1(75.81,37.604)
pads on no net: J_SWD.6 J_SWD.7 J_SWD.8 J_USB.5 J_USB.11 J_USB.NPTH-1 J_USB.NPTH-2 U_LDO.4 U_MAIN.1 U_MAIN.2 U_MAIN.3 U_MAIN.4 U_MAIN.5 U_MAIN.6 U_MAIN.7 U_MAIN.8 U_MAIN.9 U_MAIN.10 U_MAIN.11 U_MAIN.14 U_MAIN.15 U_MAIN.16 U_MAIN.17 U_MAIN.18 U_MAIN.19 U_MAIN.20 U_MAIN.21 U_MAIN.22 U_MAIN.23 U_MAIN.24 U_MAIN.25 U_MAIN.26 U_MAIN.27 U_MAIN.28 U_MAIN.33 U_MAIN.34 U_MAIN.35 U_MAIN.36 U_MAIN.37 U_MAIN.39 U_MAIN.43 U_MAIN.44 U_MAIN.45 U_MAIN.46 U_MAIN.49 U_MAIN.52 U_MAIN.53 U_MAIN.54 U_MAIN.55 U_MAIN.56 U_MAIN.57 U_MAIN.58 U_MAIN.59 U_MAIN.60 U_MAIN.61 U_MAIN.62 U_MAIN.63 U_MAIN.64 U_SENSOR.8
copper on no net:
  other v2: 37.2,44.4

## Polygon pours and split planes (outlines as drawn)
GND on Bottom (solid): 93.1,65.1 25.7,65.1 25.7,50.296 25.725,50.326 25.854,50.432 26.001,50.51 26.16,50.559 26.326,50.575 26.476,50.575 26.476,50.325 26.326,50.325 26.209,50.314 26.096,50.279 25.993,50.224 25.902,50.149 25.827,50.058 25.772,49.955 25.747,49.875 25.7,49.875 25.7,49.575 25.747,49.575 25.772,49.496 25.827,49.392 25.902,49.301 25.993,49.226 26.096,49.171 26.209,49.137 26.326,49.125 26.476,49.125 26.476,48.875 26.326,48.875 26.16,48.891 26.001,48.94 25.854,49.018 25.725,49.124 25.7,49.154 25.7,41.646 25.725,41.676 25.854,41.782 26.001,41.86 26.16,41.909 26.326,41.925 26.476,41.925 26.476,41.675 26.326,41.675 26.209,41.663 26.096,41.629 25.993,41.574 25.902,41.499 25.827,41.408 25.772,41.304 25.747,41.225 25.7,41.225 25.7,40.925 25.747,40.925 25.772,40.845 25.827,40.742 25.902,40.651 25.993,40.576 26.096,40.521 26.209,40.486 26.326,40.475 26.476,40.475 26.476,40.225 26.326,40.225 26.16,40.241 26.001,40.29 25.854,40.368 25.725,40.474 25.7,40.504 25.7,25.7 93.1,25.7
GND on Bottom (solid): 53.495,61.14 53.484,61.118 53.399,61.015 53.591,61.015 53.506,61.118
GND on Bottom (solid): 53.61,60.996 53.61,60.804 53.713,60.889 53.735,60.9 53.713,60.911
GND on Bottom (solid): 57.305,61.14 57.294,61.118 57.2,61.005 57.087,60.911 57.065,60.9 57.087,60.889 57.2,60.795 57.294,60.682 57.305,60.66 57.316,60.682 57.41,60.795 57.523,60.889 57.545,60.9 57.523,60.911 57.41,61.005 57.316,61.118
GND on Bottom (solid): 56.035,61.14 56.024,61.118 55.93,61.005 55.817,60.911 55.795,60.9 55.817,60.889 55.93,60.795 56.024,60.682 56.035,60.66 56.046,60.682 56.14,60.795 56.253,60.889 56.275,60.9 56.253,60.911 56.14,61.005 56.046,61.118
GND on Bottom (solid): 54.765,61.14 54.754,61.118 54.66,61.005 54.547,60.911 54.525,60.9 54.547,60.889 54.66,60.795 54.754,60.682 54.765,60.66 54.776,60.682 54.87,60.795 54.983,60.889 55.005,60.9 54.983,60.911 54.87,61.005 54.776,61.118

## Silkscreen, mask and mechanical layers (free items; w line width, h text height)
Top Overlay:
  text "3V3 • SWD • 2L" at 37.4,62.9 h0.48
  text "I2C 0x29 • USB-C FS" at 78.4,62.9 h0.5
  text "MSPM0G5117SPMR • NATIVE USB" at 48.4,28.525 h0.52
  text "VL53L4CDV0DH/1" at 81.4,28.525 h0.55
  text "QUICK CONFIGURE • SENSOR BOARD" at 64.4,27.9 h0.65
